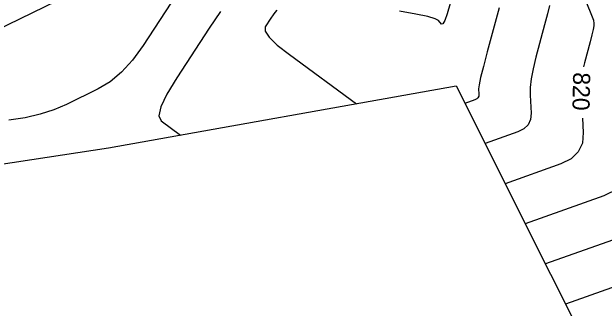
# Model space of a CAD drawing. Extents: x 1715724 to 1716561, y 394063 to 395906.
# Drawn here: x 1715987.43 to 1716035.77, y 394975.23 to 394999.44 of the extents above; entities that cross this region are included whole.
import ezdxf

# ---------------------------------------------------------------- set-up
doc = ezdxf.new("R2010")
doc.units = 0
for name, color, linetype in [('DT_X_Contour_Major', 7, 'Continuous'), ('DT_X_Contour_Minor', 7, 'Continuous'), ('DT_X_TIN_Hull', 7, 'Continuous')]:
    doc.layers.add(name, color=color, linetype=linetype)

msp = doc.modelspace()

# ---------------------------------------------------------------- linework, layer by layer
at = {"layer": 'DT_X_Contour_Major'}
for points in [[(1716000.412, 395000.161), (1715998.142, 394996.693), (1715997.276, 394995.495), (1715996.377, 394994.504), (1715995.447, 394993.719), (1715994.486, 394993.141), (1715991.881, 394991.874), (1715990.855, 394991.437), (1715989.732, 394991.076), (1715988.511, 394990.791), (1715987.193, 394990.583)], [(1716034.318, 395000.186), (1716034.738, 394999.181), (1716034.89, 394998.773), (1716034.939, 394998.484), (1716034.934, 394998.309), (1716034.881, 394998.002), (1716034.78, 394997.561), (1716034.631, 394996.988), (1716034.169, 394995.283), (1716034.097, 394994.942)], [(1716034.005, 394990.758), (1716034.07, 394989.593), (1716033.995, 394988.723), (1716033.663, 394988.003), (1716033.075, 394987.432), (1716032.231, 394987.011), (1716027.692, 394985.398)]]:
    msp.add_lwpolyline(points, dxfattribs=at)
at = {"layer": 'DT_X_Contour_Minor'}
for points in [[(1715993.089, 395001.311), (1715986.068, 394997.897)], [(1716023.204, 395000.112), (1716022.967, 394999.291), (1716022.771, 394998.738), (1716022.616, 394998.453), (1716022.503, 394998.435), (1716022.257, 394998.743), (1716021.989, 394998.878), (1716021.369, 394999.05), (1716020.398, 394999.26), (1716019.076, 394999.507)], [(1716031.305, 394999.954), (1716031.148, 394999.271), (1716030.917, 394998.381), (1716030.201, 394995.735), (1716029.97, 394994.796), (1716029.814, 394993.967), (1716029.733, 394993.247), (1716029.727, 394992.636), (1716029.81, 394991.15), (1716029.765, 394990.638), (1716029.57, 394990.213), (1716029.223, 394989.877), (1716028.726, 394989.629), (1716026.051, 394988.679)], [(1716004.471, 394999.476), (1716003.545, 394998.096), (1716000.906, 394994.062), (1716000.083, 394992.707), (1715999.592, 394991.668), (1715999.434, 394990.945), (1715999.609, 394990.537), (1716001.201, 394989.371)], [(1716009.049, 394999.574), (1716008.907, 394999.401), (1716008.751, 394999.188), (1716008.58, 394998.936), (1716008.105, 394998.21), (1716008.096, 394997.864), (1716008.424, 394997.372), (1716009.091, 394996.733), (1716010.096, 394995.946), (1716015.572, 394991.935)], [(1716027.203, 394999.775), (1716026.233, 394996.186), (1716025.916, 394994.988), (1716025.692, 394994.084), (1716025.561, 394993.473), (1716025.524, 394993.158), (1716025.549, 394992.708), (1716025.536, 394992.552), (1716025.476, 394992.424), (1716025.372, 394992.322), (1716025.221, 394992.247), (1716024.41, 394991.959)], [(1716036.927, 394984.987), (1716035.736, 394984.394), (1716029.332, 394982.118)], [(1716039.241, 394981.776), (1716030.973, 394978.838)], [(1716040.119, 394978.225), (1716032.613, 394975.557)]]:
    msp.add_lwpolyline(points, dxfattribs=at)
at = {"layer": 'DT_X_TIN_Hull'}
msp.add_lwpolyline([(1715915.398, 394971.824), (1715935.897, 394978.157), (1715965.259, 394983.661), (1715981.168, 394986.175), (1715995.311, 394988.32), (1716023.698, 394993.384), (1716039.082, 394962.623), (1716053.65, 394961.607), (1716061.251, 394947.632), (1716073.718, 394919.834)], dxfattribs=at)

# ---------------------------------------------------------------- texts
at = {"layer": 'DT_X_Contour_Major'}
msp.add_text('820', height=1.4, rotation=268.7482, dxfattribs=at).set_placement((1716033.245, 394994.513))

doc.saveas('drawing.dxf')
